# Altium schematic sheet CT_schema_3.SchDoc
size 276 x 169 mm
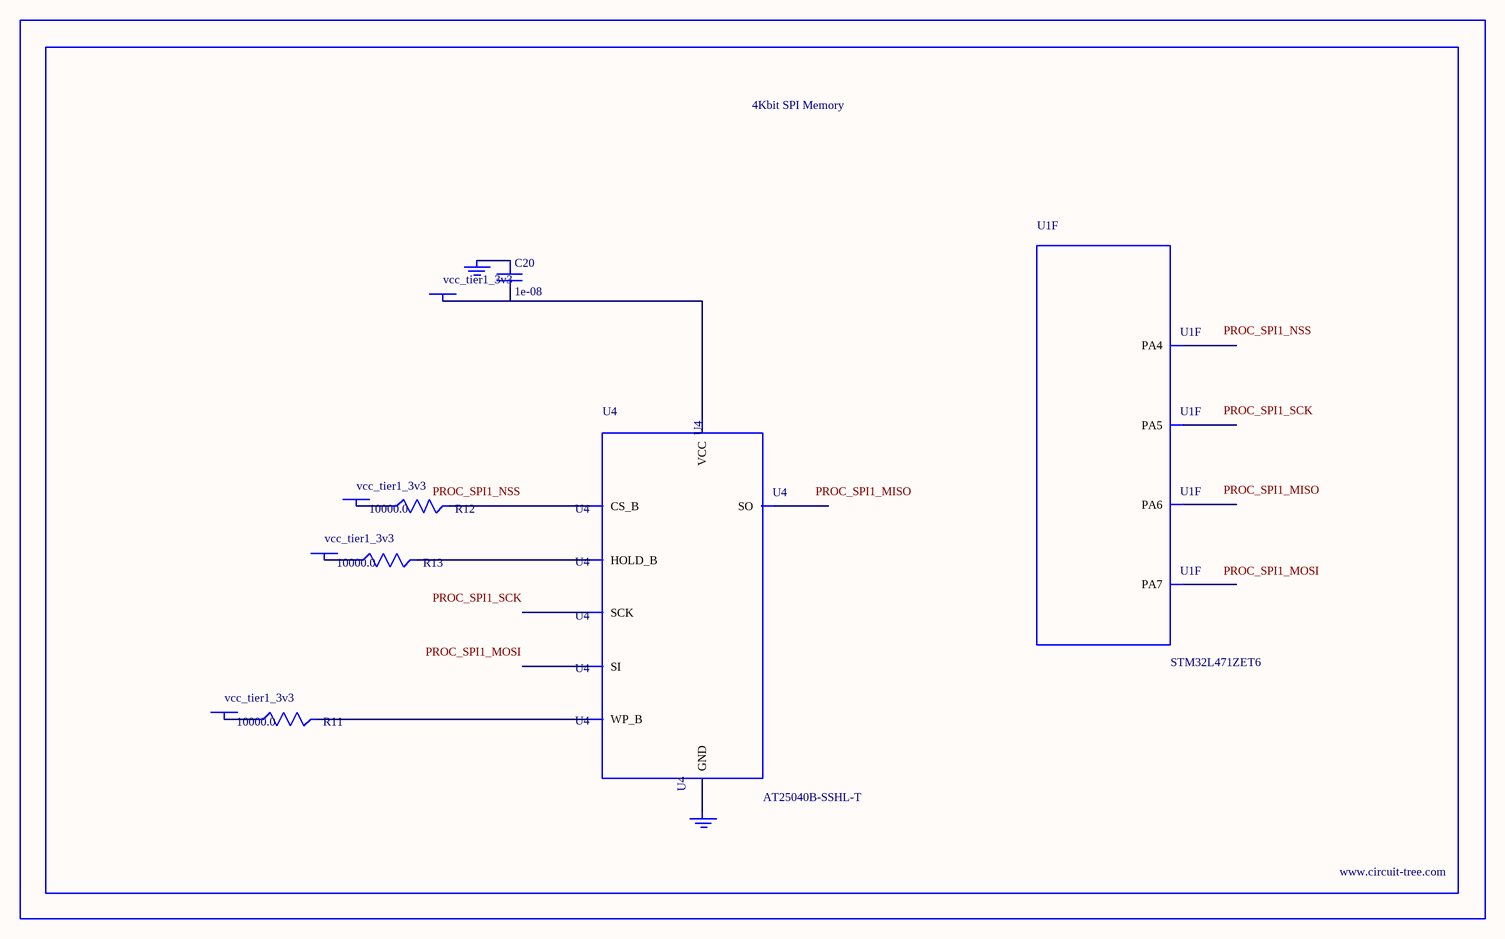
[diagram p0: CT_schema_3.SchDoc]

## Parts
BORDER2  (no value)
C20  1e-08  [C0402]
GND_INSTANCE_2_0  (no value)
GND_INSTANCE_2_1  (no value)
POWER_INSTANCE_2_0  vcc_tier1_3v3
POWER_INSTANCE_2_1  vcc_tier1_3v3
POWER_INSTANCE_2_2  vcc_tier1_3v3
POWER_INSTANCE_2_3  vcc_tier1_3v3
R11  10000.0  [R0603]
R12  10000.0  [R0603]
R13  10000.0  [R0603]
U1  STM32L471ZET6  [LQFP144]  (part F of 13)
U4  AT25040B-SSHL-T  [SOIC-8]

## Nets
NetC20_1: C20.1 GND_INSTANCE_2_0.0(GND)
NetC20_2: C20.2 POWER_INSTANCE_2_3.0(PWR) U4.8(VCC)
NetGND_INSTANCE_2_1_0: GND_INSTANCE_2_1.0(GND) U4.4(GND)
NetPOWER_INSTANCE_2_0_0: POWER_INSTANCE_2_0.0(PWR) R12.1
NetPOWER_INSTANCE_2_1_0: POWER_INSTANCE_2_1.0(PWR) R11.1
NetPOWER_INSTANCE_2_2_0: POWER_INSTANCE_2_2.0(PWR) R13.1
NetR11_2: R11.2 U4.3(WP_B)
NetR12_2: R12.2 U4.1(CS_B)
NetR13_2: R13.2 U4.7(HOLD_B)

Not connected (* = marked no-connect by the designer): U1 40(PA4) 41(PA5) 42(PA6) 43(PA7); U4 2(SO) 5(SI) 6(SCK)

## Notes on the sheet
- Labels drawn without touching a wire or pin: PROC_SPI1_MISO, PROC_SPI1_MOSI, PROC_SPI1_NSS, PROC_SPI1_SCK

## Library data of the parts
BORDER2 = BORDER_PAGE2
C20 = C0402C103K3RAC
GND_INSTANCE_2_0 GND_INSTANCE_2_1 = GND
POWER_INSTANCE_2_0-POWER_INSTANCE_2_3 = PWR
R11-R13 = RC0603JR-0710KL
